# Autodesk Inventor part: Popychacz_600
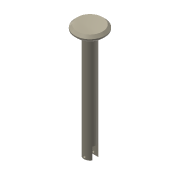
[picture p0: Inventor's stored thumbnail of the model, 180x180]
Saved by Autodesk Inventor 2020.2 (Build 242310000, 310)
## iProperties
Created: 2014-12
Part Number: Popychacz_600
Material: Ogólny
Document SubType Name: Modeling
Designer: F.Stasiak
Density: 1 g/cm^3
Appearance: Jasnobeżowa
Mass: 8.73149 g
Surface Area: 40.9402 cm^2
Volume: 8.73149 cm^3
Catalog Web Link: www.expertbooks.pl
Manager: www.cadconsulting.pl
Company: Fabian Stasiak CAD Consulting
Author: F.Stasiak
Subject: Zbiór ćwiczeń. Autodesk Inventor 2020. Kurs Professional
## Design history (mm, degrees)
sketch "Szkic1"
  geometry: C1 r 5 at (0, 0); 1 further point
  constraints: 1 centre point, 1 coincident
  dimensions: "d0" = 10 diameter of C1
extrude "Wyciągnięcie proste1" new body sketch "Szkic1" distance "d1" = 90; taper "d2" = 0 deg
sketch "Szkic2"
  geometry: C1 r 12.5 at (0, 0); 1 further point
  constraints: 1 centre point, 1 coincident
  dimensions: "d3" = 25 diameter of C1
extrude "Wyciągnięcie proste2" join sketch "Szkic2" distance "d4" = 5; taper "d5" = 0 deg
chamfer "Faza1" distance "d10" = 2; stored, may be unused: second distance "d11" = 2, angle "d12" = 45 deg
sketch "Szkic4"
  geometry: L1 (-7.5, 2.5)-(7.5, 2.5); L2 (7.5, 2.5)-(7.5, -2.5); L3 (7.5, -2.5)-(-7.5, -2.5); L4 (-7.5, -2.5)-(-7.5, 2.5); L5 (-7.5, 2.5)-(7.5, -2.5); L6 (7.5, 2.5)-(-7.5, -2.5); 1 further point
  constraints: 12 end point, 2 midpoint, 2 parallel, 1 horizontal, 1 perpendicular
  dimensions: "d13" = 15 distance of L2.end L3.end; "d14" = 5 distance of L1.end L2.end
extrude "Wyciągnięcie proste4" cut sketch "Szkic4" distance "d15" = 10; taper "d16" = 0 deg
sketch "Szkic5"
  geometry: L1 (0, 0)-(0, 10) reference; L2 (8.66, 0)-(0, 0) reference; L3 (8.66, 10)-(8.66, 0) reference; L4 (8.66, 10)-(0, 10) reference; 3 further points
  constraints: 1 midpoint, 1 vertical alignment
  dimensions: "d17" = 2 distance from line of point (4.33, 2) L2
hole "Otwór1" sketch "Szkic5" at (4.33, 2) diameter "d18" = 2; stored, may be unused: countersink angle "d22" = 90 deg, drill point angle "d24" = 118 deg; dims "d19" = 6, "d20" = 4, "d21" = 2, "d23" = 8
sketch "Szkic6"
  geometry: C1 r 1 at (4.33, -2) reference; 1 further point
extrude "Wyciągnięcie proste5" cut sketch "Szkic6" extent not by distance; stored distance "d25" = 12; taper "d26" = 0 deg
node "Bryła1"
node "Pętla rzutowana1"
